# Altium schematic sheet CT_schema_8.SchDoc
size 274 x 160 mm
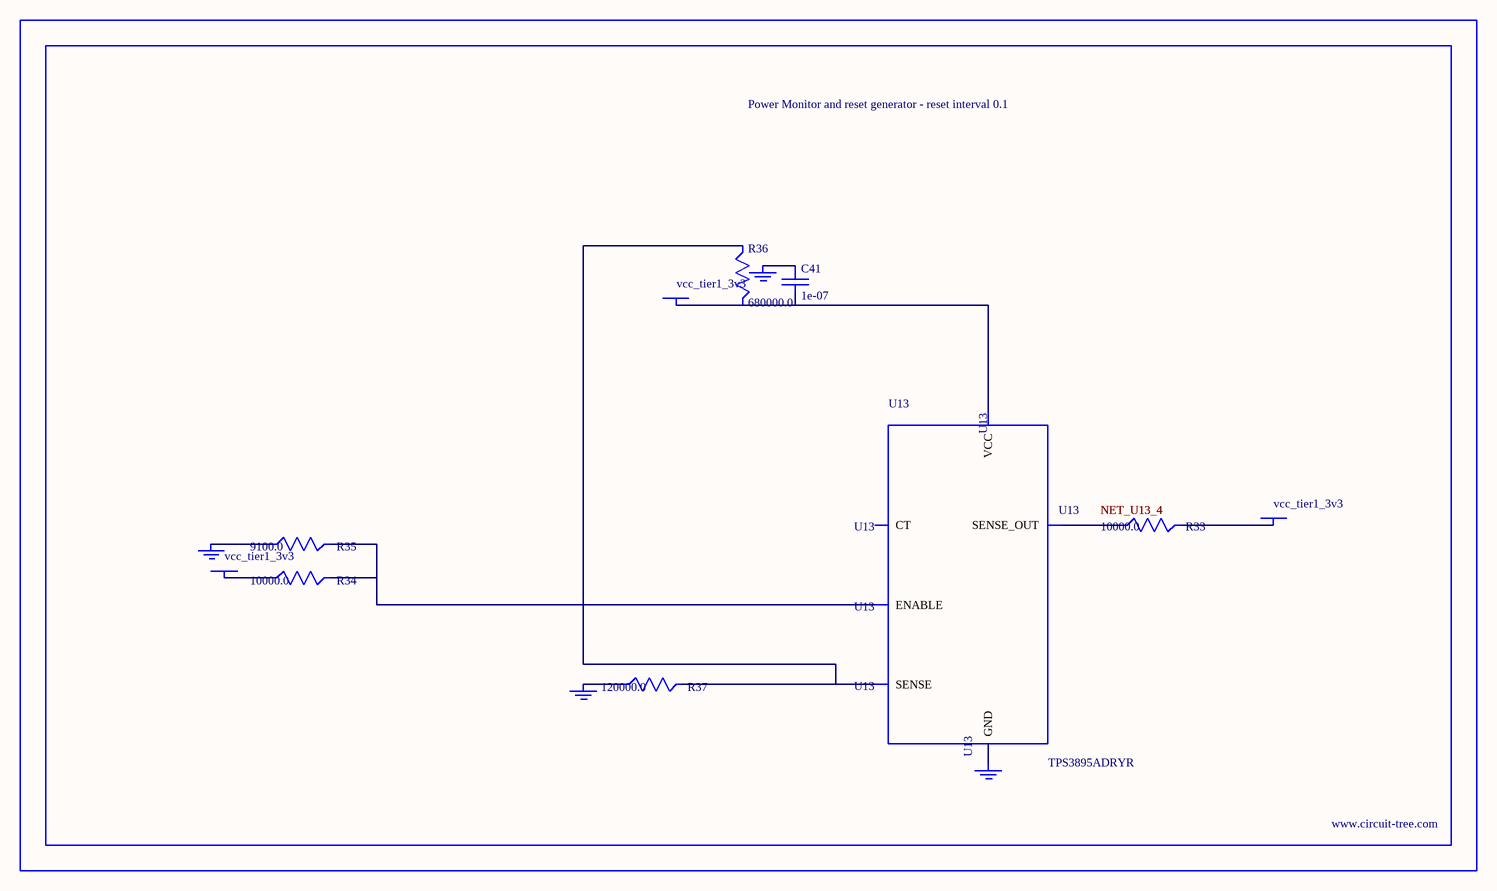
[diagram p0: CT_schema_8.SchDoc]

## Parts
BORDER7  (no value)
C41  1e-07  [C0402]
GND_INSTANCE_7_0  (no value)
GND_INSTANCE_7_1  (no value)
GND_INSTANCE_7_2  (no value)
GND_INSTANCE_7_3  (no value)
POWER_INSTANCE_7_0  vcc_tier1_3v3
POWER_INSTANCE_7_1  vcc_tier1_3v3
POWER_INSTANCE_7_2  vcc_tier1_3v3
R33  10000.0  [R0603]
R34  10000.0  [R0603]
R35  9100.0  [R0603]
R36  680000.0  [R0603]
R37  120000.0  [R0603]
U13  TPS3895ADRYR  [SON-6]

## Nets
NetC41_1: C41.1 GND_INSTANCE_7_2.0(GND)
NetC41_2: C41.2 POWER_INSTANCE_7_2.0(PWR) R36.2 U13.6(VCC)
NetGND_INSTANCE_7_0_0: GND_INSTANCE_7_0.0(GND) R35.1
NetGND_INSTANCE_7_1_0: GND_INSTANCE_7_1.0(GND) R37.1
NetGND_INSTANCE_7_3_0: GND_INSTANCE_7_3.0(GND) U13.2(GND)
NetPOWER_INSTANCE_7_0_0: POWER_INSTANCE_7_0.0(PWR) R34.1
NetPOWER_INSTANCE_7_1_0: POWER_INSTANCE_7_1.0(PWR) R33.2
NetR33_1: R33.1 U13.4(SENSE_OUT)
NetR34_2: R34.2 R35.2 U13.1(ENABLE)
NetR36_1: R36.1 R37.2 U13.3(SENSE)

Not connected (* = marked no-connect by the designer): U13 5(CT)

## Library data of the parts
BORDER7 = BORDER_PAGE7
C41 = C0402C104K3RACTU
GND_INSTANCE_7_0-GND_INSTANCE_7_3 = GND
POWER_INSTANCE_7_0-POWER_INSTANCE_7_2 = PWR
R33 R34 = RC0603JR-0710KL
R35 = RC0603JR-079K1L
R36 = RC0603JR-07680KL
R37 = RC0603JR-07120KL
